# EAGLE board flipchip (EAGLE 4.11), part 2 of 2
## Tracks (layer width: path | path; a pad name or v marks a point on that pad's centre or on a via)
A1  (via drill 0.61)
  Top 0.254: D29.2 148.59,58.89 147.31,58.89 D30.1 | v130.17,65.24 v130.17,62.06
  Bottom 0.254: 130.17,60.16 144.78,60.16 146.05,58.89 D30.1 | 130.17,60.16 129.53,60.16 128.27,58.89 IN3-4.13 | IC5.11 26.66,62.06 28.57,60.16 49.52,60.16 50.8,61.43 SV1.10 51.43,60.8 52.7,60.8 52.7,58.25 55.24,55.72 81.27,55.72 86.35,60.8 92.07,60.8 95.88,64.61 126.36,64.61 127.63,65.88 129.53,65.88 v130.17,65.24 | v130.17,62.06 130.17,60.16
A1I
  Top 0.254: IC10.11 106.67,63.33 107.94,64.61 126.99,64.61 126.99,63.97 127.63,63.33 127.63,62.06 IN3-4.15
B1  (via drill 0.61)
  Top 0.254: D39.2 148.59,69.05 147.31,69.05 D40.1 | v32.38,69.69 25.39,69.69 24.12,68.42 IC6.3 | v45.08,67.14 46.35,65.88 46.35,62.06 SV1.6 46.35,60.8 46.35,60.16 59.69,60.16 60.32,60.8 60.32,85.56 v65.4,85.56 | v120.64,84.29 120.64,83.02 122.55,81.12 122.55,69.05 124.45,69.05 IN5-6.2
  Bottom 0.254: IN5-6.2 125.72,69.05 126.99,67.78 144.78,67.78 146.05,69.05 D40.1 | v32.38,69.69 42.54,69.69 v45.08,67.14 | v120.64,84.29 109.85,84.29 108.58,83.02 97.78,83.02 95.24,85.56 v65.4,85.56
B1I
  Bottom 0.254: IC11.3 104.13,68.42 106.04,70.32 122.55,70.32 123.82,71.59 124.45,71.59 IN5-6.4
C1  (via drill 0.61)
  Top 0.254: v34.92,58.89 34.92,72.86 33.65,74.13 IC6.8 | SV1.3 44.45,58.89 45.72,58.89 SV1.5 46.98,58.89 48.26,58.89 SV1.7 49.52,58.89 50.8,58.89 SV1.9 52.06,58.89 53.34,58.89 SV1.11 54.61,58.89 55.88,58.89 SV1.13 57.15,58.89 58.41,58.89 SV1.15 | SV1.19 63.49,58.89 62.23,58.89 SV1.17 | SV1.23 69.84,58.89 71.11,58.89 SV1.25 72.38,58.89 73.65,58.89 SV1.27 74.92,58.89 76.19,58.89 SV1.29 | 80.64,58.89 80,58.89 SV1.31 | 80.64,58.89 81.27,58.89 SV1.33 | v83.18,74.77 80.64,72.23 80.64,58.89
  Bottom 0.254: D33.2 148.59,71.59 147.31,71.59 D34.1 146.05,71.59 144.78,70.32 126.36,70.32 126.36,72.23 125.09,73.5 IN5-6.6 124.45,74.13 123.82,73.5 97.15,73.5 96.52,72.86 95.24,72.86 93.34,74.77 v83.18,74.77 | v34.92,58.89 40.63,58.89 SV1.1 41.91,58.89 43.18,58.89 SV1.3 | SV1.17 60.95,58.89 59.69,58.89 SV1.15 | SV1.19 64.77,58.89 66.03,58.89 SV1.21 67.3,58.89 68.58,58.89 SV1.23 | SV1.31 78.73,58.89 77.46,58.89 SV1.29
C1I  (via drill 0.61)
  Top 0.254: v123.82,70.32 123.82,74.77 125.09,76.03 IN5-6.8
  Bottom 0.254: v123.82,70.32 123.18,69.69 113.02,69.69 111.75,68.42 IC11.6
D1  (via drill 0.61)
  Top 0.254: v47.62,65.88 48.89,64.61 | 48.89,64.61 48.89,62.06 SV1.8 | 130.17,70.95 v132.07,72.86 | 130.17,70.95 128.27,69.05 IN5-6.1 | 48.89,64.61 52.7,64.61 52.7,85.56 53.97,86.83 70.48,86.83 70.48,81.75 72.38,79.84 78.1,79.84 v78.1,43.02 | v131.44,37.3 135.25,41.11 135.25,50.64 134.62,51.27 134.62,66.51 130.17,70.95
  Bottom 0.254: v47.62,65.88 33.02,65.88 31.75,67.14 IC6.6 | v132.07,72.86 144.78,72.86 146.05,74.13 D36.1 147.31,74.13 148.59,74.13 D35.2 | v78.1,43.02 78.73,42.38 89.53,42.38 92.7,39.2 129.53,39.2 v131.44,37.3
D1I
  Bottom 0.254: IC11.8 114.29,75.4 125.72,75.4 126.36,74.77 126.36,73.5 127.63,72.23 IN5-6.3
D2  (via drill 0.61)
  Top 0.254: v125.09,15.07 125.09,17.62 IN1-2.2 | v38.09,41.75 38.09,22.7 29.21,22.7 24.12,17.62 IC20.3 | v75.56,41.75 76.83,43.02 76.83,45.56 SV2.6 | v89.53,13.8 88.26,15.07 v88.26,37.94
  Bottom 0.254: D1.1 148.59,13.17 147.31,13.17 D2.2 146.05,13.17 144.78,14.44 140.33,14.44 139.7,15.07 v125.09,15.07 124.45,14.44 100.96,14.44 99.69,15.71 99.05,15.07 90.8,15.07 v89.53,13.8 | v38.09,41.75 39.37,43.02 50.16,43.02 50.8,42.38 68.58,42.38 69.21,41.75 v75.56,41.75 84.45,41.75 v88.26,37.94
D2I
  Bottom 0.254: IC2.3 103.5,18.25 105.4,20.16 118.1,20.16 119.38,21.43 125.09,21.43 IN1-2.4
E1  (via drill 0.61)
  Top 0.254: v158.75,5.55 157.47,6.82 157.47,72.86 151.12,72.86 150.49,73.5 150.49,74.77 149.22,76.03 D37.2
  Bottom 0.254: IN5-6.5 128.27,74.13 139.06,74.13 140.33,75.4 144.78,75.4 146.05,76.67 D38.1 147.31,76.67 148.59,76.67 D37.2 | 29.84,64.61 29.84,69.05 29.21,69.69 26.03,69.69 26.03,74.13 IC6.11 | 29.84,64.61 48.89,64.61 50.8,62.7 52.06,62.7 53.34,61.43 SV1.12 | v158.75,5.55 156.84,3.64 142.87,3.64 141.6,2.38 85.72,2.38 84.45,3.64 79.37,3.64 77.46,1.74 23.49,1.74 8.25,16.98 7.62,16.98 6.98,17.62 6.98,64.61 29.84,64.61
E1I
  Bottom 0.254: IC11.11 106.67,76.03 108.58,77.94 125.72,77.94 126.99,76.67 IN5-6.7
E2  (via drill 0.61)
  Top 0.254: v145.41,19.52 145.41,17.62 146.68,16.34 D4.2 | v62.86,24.6 v65.4,24.6 | v74.29,24.6 75.56,25.87 75.56,40.47 74.29,41.75 74.29,45.56 SV2.8 | v122.55,20.16 125.09,22.7 IN1-2.6
  Bottom 0.254: v145.41,19.52 139.06,19.52 136.52,22.06 126.99,22.06 125.72,23.33 IN1-2.6 | D3.1 148.59,15.71 147.31,15.71 D4.2 | v62.86,24.6 34.28,24.6 IC20.8 | v65.4,24.6 v74.29,24.6 74.92,25.23 78.1,25.23 78.73,24.6 90.8,24.6 93.34,22.06 102.23,22.06 102.23,15.71 102.86,15.07 104.77,15.07 104.77,18.25 106.04,19.52 118.74,19.52 119.38,20.16 v122.55,20.16
E2I  (via drill 0.61)
  Top 0.254: v121.28,18.88 121.28,21.43 125.09,25.23 IN1-2.8
  Bottom 0.254: v121.28,18.88 113.02,18.88 111.75,17.62 IC2.6
F1  (via drill 0.61)
  Top 0.254: v113.02,72.23 v120.01,79.21
  Bottom 0.254: D47.2 148.59,79.21 147.31,79.21 D48.1 146.05,79.21 144.78,77.94 126.99,77.94 125.72,79.21 IN5-6.10 124.45,79.21 v120.01,79.21 | 62.86,64.61 52.7,64.61 39.37,77.94 26.03,77.94 24.12,79.84 IC7.3 | 62.86,64.61 65.4,62.06 65.4,60.16 58.41,60.16 57.15,61.43 SV1.14 | v113.02,72.23 71.11,72.23 70.48,71.59 70.48,64.61 62.86,64.61
F1I  (via drill 0.61)
  Top 0.254: v104.77,92.55 104.77,83.02 103.5,81.75 IC12.3 | v116.83,93.18 119.38,90.64 119.38,86.83 124.45,81.75 IN5-6.12
  Bottom 0.254: v104.77,92.55 106.04,93.81 116.2,93.81 v116.83,93.18
F2  (via drill 0.61)
  Top 0.254: SV2.10 71.75,46.83 71.75,47.46 66.03,47.46 65.4,46.83 65.4,39.2 60.32,34.12 60.32,15.07 v59.69,14.44 v67.94,6.18 | v156.21,2.38 156.21,16.98 151.12,16.98 149.86,18.25 D5.1 | v84.45,2.38 77.46,2.38 v77.46,3.01 | v74.29,3.01 73.65,3.01 73.02,2.38 71.75,2.38 v71.75,3.64
  Bottom 0.254: IN1-2.1 128.27,18.25 129.53,16.98 144.78,16.98 146.05,18.25 D6.2 147.31,18.25 148.59,18.25 D5.1 | v59.69,14.44 33.65,14.44 31.75,16.34 IC20.6 | v156.21,2.38 155.57,1.74 85.08,1.74 v84.45,2.38 | v74.29,3.01 v77.46,3.01 | v71.75,3.64 70.48,3.64 v67.94,6.18
F2I
  Bottom 0.254: IC2.8 114.29,23.96 122.55,23.96 124.45,22.06 125.72,22.06 126.99,20.79 IN1-2.3
H1  (via drill 0.61)
  Top 0.254: v53.97,85.56 57.78,85.56 57.78,63.33 59.05,62.06 SV1.16 | IN5-6.14 125.09,84.92 123.82,86.2 v123.82,90.01 123.82,93.81 125.72,95.72 125.72,99.53 133.98,99.53 134.62,98.9 134.62,93.18 v133.98,92.55
  Bottom 0.254: D42.1 147.31,81.75 148.59,81.75 D41.2 149.22,82.39 150.49,83.66 150.49,85.56 155.57,85.56 156.21,86.2 156.21,88.1 151.76,88.1 149.22,90.64 138.43,90.64 136.52,92.55 v133.98,92.55 | IC7.8 34.28,87.47 36.19,85.56 v53.97,85.56 55.24,86.83 88.26,86.83 91.43,90.01 v123.82,90.01
H1I  (via drill 0.61)
  Top 0.254: v140.97,96.36 140.97,101.44 123.82,101.44 112.39,90.01 112.39,83.02 111.12,81.75 IC12.6 | v138.43,95.72 136.52,93.81 v136.52,87.47
  Bottom 0.254: v140.97,96.36 140.33,95.72 v138.43,95.72 | v136.52,87.47 135.89,88.1 126.99,88.1 125.72,86.83 IN5-6.16
H2  (via drill 0.61)
  Top 0.254: D7.1 148.59,20.79 147.31,20.79 D8.2 | v36.82,41.75 36.82,27.77 29.21,27.77 26.66,25.23 IC20.11 | v69.21,43.02 69.21,45.56 SV2.12 | v139.06,20.79 139.06,4.28 114.93,4.28 114.93,18.25 v111.12,22.06 | v95.88,25.23 95.88,29.04 94.61,30.32 v94.61,44.92
  Bottom 0.254: 140.33,22.06 139.7,22.7 128.9,22.7 128.27,23.33 IN1-2.5 | 140.33,22.06 144.78,22.06 146.05,20.79 D8.2 | v36.82,41.75 38.73,43.65 50.8,43.65 51.43,43.02 v69.21,43.02 73.02,43.02 74.29,44.28 93.97,44.28 v94.61,44.92 | v139.06,20.79 140.33,22.06 | v111.12,22.06 110.48,22.7 97.78,22.7 97.15,23.33 97.15,25.23 v95.88,25.23
H2I
  Bottom 0.254: IC2.11 106.67,25.23 108.58,27.14 125.72,27.14 126.99,25.87 IN1-2.7
J1  (via drill 0.61)
  Top 0.254: v40,71.59 39.37,72.23 | 39.37,72.23 31.75,79.84 IC7.6 | v123.82,95.09 125.09,96.36 125.09,100.17 134.62,100.17 135.25,99.53 135.25,75.4 133.98,75.4 130.17,79.21 128.27,79.21 IN5-6.9 | v115.56,95.72 112.39,98.9 112.39,102.7 111.12,103.98 39.37,103.98 39.37,72.23
  Bottom 0.254: IN5-6.9 128.27,79.21 130.17,79.21 133.98,83.02 144.78,83.02 146.05,84.29 D44.1 147.31,84.29 148.59,84.29 D43.2 | v40,71.59 40.63,70.95 45.08,70.95 52.06,63.97 60.95,63.97 63.49,61.43 SV1.20 | v123.82,95.09 123.18,94.45 116.83,94.45 v115.56,95.72
J1I  (via drill 0.61)
  Top 0.254: v116.2,82.39 116.2,84.29 113.66,86.83 IC12.8 | v123.18,81.75 124.45,80.48 126.99,80.48 126.99,81.75 IN5-6.11
  Bottom 0.254: v116.2,82.39 116.83,81.75 v123.18,81.75
J2  (via drill 0.61)
  Top 0.254: D16.1 148.59,23.33 147.31,23.33 D15.2 | SV2.14 66.67,45.56 66.67,38.57 v65.4,37.3 65.4,33.49 67.94,30.95 67.94,7.46 v69.21,6.18 | v120.01,9.99 120.01,22.7 125.09,27.77 IN1-2.10
  Bottom 0.254: IN1-2.10 125.72,28.41 126.99,27.14 128.27,27.14 129.53,25.87 139.06,25.87 140.33,24.6 144.78,24.6 146.05,23.33 D15.2 | v65.4,37.3 40,37.3 38.09,39.2 32.38,39.2 32.38,28.41 31.75,27.77 25.39,27.77 24.12,29.04 IC1.3 | v120.01,9.99 119.38,10.63 103.5,10.63 102.86,9.99 100.32,9.99 96.52,6.18 v69.21,6.18
J2I
  Bottom 0.254: IC3.3 104.13,29.04 105.4,27.77 119.38,27.77 122.55,30.95 124.45,30.95 IN1-2.12
K1  (via drill 0.61)
  Top 0.254: v32.38,73.5 32.38,76.67 29.84,79.21 29.84,83.02 26.03,86.83 IC7.11 | v62.86,80.48 62.86,63.33 61.59,62.06 SV1.18
  Bottom 0.254: D45.2 148.59,86.83 147.31,86.83 D46.1 146.05,86.83 144.78,85.56 140.33,85.56 139.06,84.29 128.27,84.29 IN5-6.13 126.99,84.29 125.72,83.02 116.83,83.02 116.2,83.66 110.48,83.66 109.21,82.39 97.15,82.39 96.52,83.02 83.81,83.02 80.64,79.84 71.11,79.84 70.48,80.48 v62.86,80.48 | v32.38,73.5 35.55,70.32 44.45,70.32 51.43,63.33 59.05,63.33 60.95,61.43 SV1.18
K1I  (via drill 0.61)
  Top 0.254: v106.04,92.55 106.04,89.37 IC12.11 | v126.36,92.55 126.36,88.73 127.63,87.47 IN5-6.15
  Bottom 0.254: v106.04,92.55 106.67,91.91 125.72,91.91 v126.36,92.55
K2  (via drill 0.61)
  Top 0.254: 125.09,32.86 126.36,31.59 126.36,30.32 126.99,29.68 v133.34,29.68 | 125.09,32.86 IN1-2.14 125.09,32.86 | v59.05,34.76 64.13,39.84 64.13,45.56 SV2.16 64.13,46.83 65.4,48.09 65.4,50 72.38,50 73.02,49.36 73.02,45.56 70.48,43.02 v70.48,4.92 | 125.09,32.86 122.55,30.32 122.55,27.14 116.83,21.43 v116.83,9.36 | v103.5,6.18 v103.5,9.36
  Bottom 0.254: v133.34,29.68 147.31,29.68 147.95,29.04 147.95,26.5 | 147.95,26.5 146.68,26.5 D9.2 | 147.95,26.5 148.59,25.87 D10.1 | v59.05,34.76 36.19,34.76 34.28,36.66 IC1.8 | v116.83,9.36 116.2,9.99 104.13,9.99 v103.5,9.36 | v103.5,6.18 102.23,4.92 v70.48,4.92
K2I  (via drill 0.61)
  Top 0.254: v115.56,35.39 111.12,30.95 IC3.6
  Bottom 0.254: v115.56,35.39 116.2,36.03 124.45,36.03 IN1-2.16
L1  (via drill 0.61)
  Top 0.254: IC8.3 64.13,69.05 69.21,63.97 69.21,62.06 SV1.24 | 81.91,9.99 75.56,3.64 75.56,3.01 74.29,1.74 48.89,1.74 48.89,12.54 D55.2 | 81.91,9.99 86.99,15.07 IN7-8.2 | v79.37,56.98 80.64,55.72 80.64,32.86 82.54,30.95 82.54,16.34 81.91,15.71 81.91,9.99
  Bottom 0.254: D56.1 46.98,13.17 48.26,13.17 D55.2 | v79.37,56.98 70.48,56.98 70.48,59.53 69.21,60.8 SV1.24
L1I
  Bottom 0.254: IC13.3 69.84,13.8 71.11,12.54 72.38,12.54 73.02,13.17 73.02,18.88 86.99,18.88 IN7-8.4
L2  (via drill 0.61)
  Top 0.254: D12.1 148.59,28.41 147.31,28.41 D11.2 | v35.55,51.27 35.55,35.39 31.11,30.95 IC1.6 | v58.41,51.27 60.32,49.36 60.32,48.09 61.59,46.83 SV2.18 61.59,45.56 57.78,41.75 57.78,32.22 57.15,31.59 57.15,15.71 v66.03,6.82 | v121.91,11.27 121.91,11.9 123.18,13.17 123.18,19.52 125.72,19.52 126.36,20.16 126.36,26.5 127.63,27.77 IN1-2.9
  Bottom 0.254: IN1-2.9 128.27,28.41 129.53,27.14 144.78,27.14 146.05,28.41 D11.2 | v35.55,51.27 v58.41,51.27 | v121.91,11.27 121.28,11.9 81.91,11.9 77.46,7.46 66.67,7.46 v66.03,6.82
L2I
  Top 0.254: IC3.8 114.29,36.66 123.82,36.66 123.82,35.39 124.45,34.76 125.72,34.76 126.36,34.12 126.36,32.86 127.63,31.59 IN1-2.11
M1  (via drill 0.61)
  Top 0.254: IC8.8 74.29,76.67 75.56,75.4 75.56,63.33 74.29,62.06 SV1.28 | v84.45,15.71 84.45,17.62 86.99,20.16 IN7-8.6 | v54.61,7.46 50.16,11.9 50.16,13.8 48.89,15.07 D49.2 | v93.34,73.5 93.97,72.86 93.97,65.24 92.07,63.33 v92.07,22.06
  Bottom 0.254: v84.45,15.71 76.83,8.09 55.24,8.09 v54.61,7.46 | D50.1 46.98,15.71 48.26,15.71 D49.2 | v93.34,73.5 78.73,73.5 74.92,77.31 IC8.8 | v92.07,22.06 88.89,22.06 87.62,20.79 IN7-8.6
M1I  (via drill 0.61)
  Top 0.254: v78.1,23.96 78.1,16.98 76.83,15.71 IC13.6
  Bottom 0.254: v78.1,23.96 86.99,23.96 IN7-8.8
M2  (via drill 0.61)
  Top 0.254: D14.1 148.59,30.95 147.31,30.95 D13.2 | v52.06,39.84 58.41,46.19 SV2.20
  Bottom 0.254: D13.2 146.05,30.95 144.78,32.22 129.53,32.22 128.27,33.49 IN1-2.13 126.99,33.49 125.72,32.22 121.91,32.22 121.28,32.86 92.07,32.86 85.08,39.84 v52.06,39.84 28.57,39.84 26.66,37.94 IC1.11
M2I
  Top 0.254: IC3.11 106.04,38.57 107.94,40.47 127.63,40.47 127.63,36.66 IN1-2.15
N1  (via drill 0.61)
  Top 0.254: v86.35,63.33 86.35,42.38 90.8,37.94 90.8,17.62 89.53,16.34 IN7-8.1 | D51.2 48.89,18.88 50.16,20.16 50.16,40.47 55.24,45.56 55.24,49.36 63.49,57.62 65.4,57.62 65.4,59.53 66.67,60.8 SV1.22
  Bottom 0.254: D52.1 46.98,18.25 48.26,18.25 D51.2 | 71.75,63.97 71.75,62.7 68.58,62.7 67.3,61.43 SV1.22 | 71.75,63.97 71.75,69.05 IC8.6 | v86.35,63.33 85.72,63.97 71.75,63.97
N1I  (via drill 0.61)
  Top 0.254: v80,17.62 80,20.16 79.37,20.79 IC13.8
  Bottom 0.254: v80,17.62 80.64,16.98 87.62,16.98 88.89,18.25 IN7-8.3
N2  (via drill 0.61)
  Top 0.254: v138.43,45.56 137.79,44.92 137.79,38.57 139.06,37.3 146.68,37.3 146.68,40.47 D24.1 147.31,41.11 148.59,41.11 D23.2 | v52.06,41.11 56.51,45.56 SV2.22 | v107.31,44.28 104.77,46.83 v104.77,51.91
  Bottom 0.254: v138.43,45.56 133.98,45.56 133.34,44.92 126.99,44.92 125.72,43.65 IN3-4.2 124.45,43.65 123.82,44.28 v107.31,44.28 | v52.06,41.11 51.43,40.47 25.39,40.47 24.12,41.75 IC4.3 | v104.77,51.91 60.32,51.91 57.78,49.36 57.78,46.83 56.51,46.83 SV2.22
N2I
  Bottom 0.254: IC9.3 104.13,43.02 106.67,45.56 125.09,45.56 IN3-4.4
N$1  (via drill 0.61)
  Top 0.254: v116.83,62.06 116.83,60.8 109.21,60.8 104.77,56.35 104.77,53.81 102.23,51.27 102.23,48.73 101.59,48.09 101.59,44.28 100.96,43.65 IC9.2 | v128.9,57.62 132.71,53.81 132.71,43.02 133.98,41.75 v133.98,41.11 | D24.2 143.5,41.11 142.87,41.11 RN4.11
  Bottom 0.254: v116.83,62.06 117.47,62.7 125.72,62.7 126.36,62.06 126.36,58.25 126.99,57.62 v128.9,57.62 | v133.98,41.11 140.33,41.11 RN4.11
N$2  (via drill 0.61)
  Top 0.254: RN3.11 153.03,41.11 152.4,41.11 D23.1 | v90.8,42.38 91.43,43.02 91.43,66.51 90.8,67.14 v90.8,95.09 | v138.43,94.45 139.06,93.81 139.06,76.67 135.89,73.5 135.89,56.98 139.06,53.81 139.06,47.46 136.52,44.92 v136.52,42.38
  Bottom 0.254: v90.8,42.38 97.78,42.38 IC9.1 | v90.8,95.09 112.39,95.09 114.93,97.62 125.72,97.62 126.99,98.9 133.98,98.9 v138.43,94.45 | v136.52,42.38 149.86,42.38 151.12,41.11 D23.1
N$3  (via drill 0.61)
  Top 0.254: RN1.11 153.03,13.17 152.4,13.17 D1.2 151.76,12.54 v151.76,9.99 | v100.96,8.72 100.96,15.71 IC2.2
  Bottom 0.254: v100.96,8.72 102.86,8.72 103.5,8.09 106.67,8.09 107.31,7.46 123.18,7.46 124.45,6.18 137.79,6.18 141.6,9.99 v151.76,9.99
N$4  (via drill 0.61)
  Top 0.254: v104.77,3.64 98.42,9.99 98.42,15.71 IC2.1 | v141.6,3.64 141.6,12.54 RN2.11 142.87,13.17 143.5,13.17 D2.1
  Bottom 0.254: v104.77,3.64 v141.6,3.64
N$5
  Top 0.254: D18.2 143.5,43.65 142.87,43.65 RN4.10
  Bottom 0.254: IC9.5 109.21,41.75 111.12,39.84 131.44,39.84 135.25,43.65 140.33,43.65 RN4.10
N$6
  Top 0.254: RN1.10 153.03,15.71 152.4,15.71 D3.2 151.76,15.07 150.49,13.8 150.49,1.74 111.75,1.74 108.58,4.92 108.58,15.71 IC2.5
N$7  (via drill 0.61)
  Top 0.254: v104.77,6.18 104.77,39.84 106.04,41.11 IC9.4 | v158.75,7.46 v158.75,44.28 | RN3.10 153.03,43.65 152.4,43.65 D17.1
  Bottom 0.254: v104.77,6.18 121.91,6.18 123.18,4.92 140.33,4.92 142.87,7.46 v158.75,7.46 | v158.75,44.28 155.57,47.46 151.12,47.46 150.49,46.83 150.49,44.28 151.76,44.28 D17.1
N$8  (via drill 0.61)
  Top 0.254: v120.64,43.02 120.64,45.56 115.56,45.56 111.75,49.36 IC9.9 | v131.44,43.02 132.71,41.75 v132.71,39.84 | D19.1 152.4,46.19 153.03,46.19 RN3.9
  Bottom 0.254: v120.64,43.02 121.28,42.38 128.9,42.38 129.53,43.02 v131.44,43.02 | v132.71,39.84 155.57,39.84 156.21,40.47 156.21,45.56 154.94,45.56 RN3.9
N$9  (via drill 0.61)
  Top 0.254: RN3.8 153.03,48.73 152.4,48.73 D21.1 151.76,48.09 150.49,46.83 150.49,36.66 v152.4,34.76 | v102.23,7.46 102.23,47.46 103.5,48.73 IC9.12
  Bottom 0.254: v102.23,7.46 106.04,7.46 106.67,6.82 122.55,6.82 123.82,5.55 138.43,5.55 140.97,8.09 153.03,8.09 158.75,13.8 158.75,34.76 v152.4,34.76
N$10  (via drill 0.61)
  Top 0.254: RN3.7 153.03,51.27 152.4,51.27 D31.1 | v97.15,65.88 97.15,57.62 98.42,56.35 IC10.1
  Bottom 0.254: v97.15,65.88 126.36,65.88 127.63,67.14 138.43,67.14 140.33,65.24 156.84,65.24 158.75,67.14 160.02,65.88 160.02,51.91 154.94,51.91 RN3.7
N$11  (via drill 0.61)
  Top 0.254: RN3.6 153.03,53.81 152.4,53.81 D25.1 | v100.96,57.62 99.69,58.89 v99.69,98.9 | v122.55,101.44 125.72,104.61 160.02,104.61 160.02,59.53 v158.75,58.25
  Bottom 0.254: v100.96,57.62 103.5,57.62 105.4,55.72 IC10.4 | v99.69,98.9 101.59,100.8 121.91,100.8 v122.55,101.44 | v158.75,58.25 154.94,54.44 RN3.6
N$12  (via drill 0.61)
  Top 0.254: v123.82,60.16 129.53,60.16 v129.53,58.89 | RN3.5 153.03,56.35 152.4,56.35 D27.1
  Bottom 0.254: v123.82,60.16 123.18,60.8 113.02,60.8 111.75,62.06 IC10.9 | v129.53,58.89 130.17,58.25 139.7,58.25 140.33,57.62 149.86,57.62 151.12,56.35 D27.1
N$13  (via drill 0.61)
  Top 0.254: RN3.4 153.03,58.89 152.4,58.89 D29.1 | v104.77,70.32 104.77,65.24 103.5,63.97 IC10.12 | v119.38,71.59 121.91,69.05 121.91,68.42 123.82,66.51 133.34,66.51 v133.34,62.06
  Bottom 0.254: v104.77,70.32 105.4,70.95 118.74,70.95 v119.38,71.59 | v133.34,62.06 133.98,62.7 147.31,62.7 151.12,58.89 D29.1
N$14  (via drill 0.61)
  Top 0.254: v133.34,56.98 133.34,57.62 128.9,62.06 128.9,63.33 127.63,64.61 127.63,65.24 106.04,65.24 104.77,63.97 104.77,60.8 106.67,60.8 107.94,62.06 IC10.10 | D28.2 143.5,56.35 142.87,56.35 RN4.5
  Bottom 0.254: v133.34,56.98 133.98,56.35 140.33,56.35 RN4.5
N$15  (via drill 0.61)
  Top 0.254: D20.2 143.5,46.19 142.87,46.19 RN4.9 140.97,45.56 139.7,44.28 139.7,39.2 v139.06,38.57 | v131.44,38.57 128.9,41.11 121.28,41.11 119.38,43.02 119.38,44.92 113.66,44.92 109.21,49.36 IC9.10
  Bottom 0.254: v131.44,38.57 v139.06,38.57
N$16  (via drill 0.61)
  Top 0.254: RN4.8 142.87,48.73 143.5,48.73 D22.2 144.14,48.09 145.41,46.83 v145.41,38.57 | v93.34,100.17 93.34,81.12 94.61,79.84 94.61,68.42 95.24,67.78 95.24,63.97 94.61,63.33 94.61,55.72 97.15,53.17 97.15,44.28 99.69,44.28 100.96,45.56 100.96,48.73 IC9.13
  Bottom 0.254: v93.34,100.17 97.78,104.61 154.3,104.61 161.28,97.62 161.28,37.3 147.95,37.3 146.68,38.57 v145.41,38.57
N$17  (via drill 0.61)
  Top 0.254: v99.69,45.56 99.69,52.54 100.96,53.81 IC10.2 | v114.93,47.46 v118.1,50.64 | v123.82,50 129.53,50 v129.53,50.64 | D32.2 143.5,51.27 142.87,51.27 RN4.7
  Bottom 0.254: v99.69,45.56 100.32,46.19 113.66,46.19 v114.93,47.46 | v118.1,50.64 118.74,50 v123.82,50 | v129.53,50.64 131.44,52.54 136.52,52.54 137.79,51.27 140.33,51.27 RN4.7
N$18
  Top 0.254: D26.2 143.5,53.81 142.87,53.81 RN4.6
  Bottom 0.254: IC10.5 109.21,54.44 110.48,53.17 123.82,53.17 124.45,52.54 129.53,52.54 130.17,53.17 137.16,53.17 137.79,53.81 140.33,53.81 RN4.6
N$19  (via drill 0.61)
  Top 0.254: RN4.4 142.87,58.89 143.5,58.89 D30.2 144.78,58.89 v148.59,62.7 | v100.96,58.89 100.96,61.43 IC10.13 | v90.16,58.25 90.16,94.45 v89.53,95.09 | v155.57,100.8 158.75,97.62 v158.75,65.88
  Bottom 0.254: v100.96,58.89 100.32,58.25 v90.16,58.25 | v89.53,95.09 95.88,101.44 121.28,101.44 122.55,102.7 142.24,102.7 144.14,100.8 v155.57,100.8 | v158.75,65.88 155.57,62.7 v148.59,62.7
N$20  (via drill 0.61)
  Top 0.254: v102.23,53.17 102.23,65.24 100.96,66.51 IC11.2 | v90.16,53.17 89.53,52.54 v89.53,40.47 | v109.21,34.12 109.85,33.49 v109.85,4.92 | v157.47,5.55 156.84,6.18 156.84,63.97 155.57,65.24 144.14,65.24 144.14,68.42 D40.2 143.5,69.05 142.87,69.05 RN6.11
  Bottom 0.254: v90.16,53.17 v102.23,53.17 | v89.53,40.47 95.88,34.12 v109.21,34.12 | v109.85,4.92 110.48,4.28 140.97,4.28 142.24,5.55 v157.47,5.55
N$21
  Top 0.254: D4.1 143.5,15.71 142.87,15.71 RN2.10
  Bottom 0.254: IC2.4 106.67,16.34 107.94,15.07 123.82,15.07 125.09,16.34 140.97,16.34 RN2.10
N$22  (via drill 0.61)
  Top 0.254: v92.7,70.95 92.07,71.59 v92.07,91.91 | v126.99,97.62 128.27,98.9 133.34,98.9 v133.34,97.62 | v146.68,93.18 147.95,91.91 147.95,70.95 148.59,70.32 151.76,70.32 151.76,69.69 D39.1 152.4,69.05 153.03,69.05 RN5.11
  Bottom 0.254: v92.7,70.95 96.52,70.95 98.42,69.05 IC11.1 | v92.07,91.91 94.61,94.45 113.02,94.45 115.56,96.99 126.36,96.99 v126.99,97.62 | v133.34,97.62 137.79,93.18 v146.68,93.18
N$23  (via drill 0.61)
  Top 0.254: RN1.9 153.03,18.25 152.4,18.25 D5.2 | v137.79,24.6 140.33,22.06 v147.95,22.06
  Bottom 0.254: v137.79,24.6 124.45,24.6 122.55,26.5 110.48,26.5 109.21,25.23 IC2.10 | v147.95,22.06 147.95,19.52 149.86,19.52 151.12,18.25 D5.2
N$24  (via drill 0.61)
  Top 0.254: v118.1,21.43 118.74,20.79 v118.74,17.62 | D6.1 143.5,18.25 142.87,18.25 RN2.9
  Bottom 0.254: v118.1,21.43 114.29,21.43 111.75,23.96 IC2.9 | v118.74,17.62 122.55,17.62 124.45,19.52 137.79,19.52 139.06,18.25 140.33,18.25 RN2.9
N$25  (via drill 0.61)
  Top 0.254: v120.64,67.14 120.64,65.88 110.48,65.88 109.21,67.14 IC11.5 | v123.82,67.78 126.36,67.78 126.36,72.23 126.99,72.86 v130.81,72.86 | D34.2 143.5,71.59 142.87,71.59 RN6.10
  Bottom 0.254: v120.64,67.14 121.28,67.78 v123.82,67.78 | v130.81,72.86 132.07,71.59 140.33,71.59 RN6.10
N$26
  Top 0.254: IC6.2 20.32,68.42 18.41,70.32 8.25,70.32 8.25,69.69 OUT5-6.2
N$33
  Top 0.254: IC4.5 27.94,43.02 26.03,44.92 10.79,44.92 10.79,44.28 OUT3-4.1
N$34
  Bottom 0.254: IC4.4 25.39,43.02 22.22,46.19 11.43,46.19 OUT3-4.3
N$35
  Bottom 0.254: IC4.12 22.86,49.36 20.95,47.46 12.7,47.46 11.43,48.73 OUT3-4.5
N$36
  Bottom 0.254: IC4.13 20.32,50.64 19.05,51.91 10.79,51.91 OUT3-4.7
N$49
  Bottom 0.254: IC4.1 18.41,43.65 17.14,44.92 10.16,44.92 8.88,46.19 OUT3-4.4
N$50
  Top 0.254: IC4.9 30.48,49.36 28.57,47.46 8.25,47.46 8.25,48.09 OUT3-4.6
N$51
  Bottom 0.254: IC4.2 20.32,41.75 19.05,40.47 12.06,40.47 8.88,43.65 OUT3-4.2
N$52
  Top 0.254: IC4.10 27.94,50.64 26.03,52.54 8.25,52.54 8.25,51.91 OUT3-4.8
N$53
  Top 0.254: IC20.5 27.94,16.34 26.66,15.07 10.79,15.07 10.79,17.62 OUT1-2.1
N$54
  Bottom 0.254: IC20.4 25.39,17.62 22.22,20.79 11.43,20.79 OUT1-2.3
N$55
  Bottom 0.254: IC20.12 22.86,23.96 20.95,22.06 12.7,22.06 11.43,23.33 OUT1-2.5
N$56
  Bottom 0.254: IC20.13 20.32,25.23 19.05,26.5 10.79,26.5 OUT1-2.7
N$57
  Bottom 0.254: IC20.2 20.32,16.34 19.05,15.07 12.06,15.07 8.88,18.25 OUT1-2.2
N$58
  Bottom 0.254: IC20.1 18.41,18.25 17.14,19.52 10.16,19.52 8.88,20.79 OUT1-2.4
N$59
  Bottom 0.254: IC20.9 30.48,23.96 27.94,21.43 12.06,21.43 11.43,22.06 10.16,22.06 8.88,23.33 OUT1-2.6
N$60
  Top 0.254: IC20.10 27.94,23.96 26.03,22.06 9.52,22.06 9.52,23.96 8.25,25.23 OUT1-2.8
N$61
  Bottom 0.254: IC1.13 20.32,37.94 19.05,39.2 14.6,39.2 11.43,36.03 OUT1-2.15
N$62
  Top 0.254: IC1.12 22.86,36.66 19.68,33.49 11.43,33.49 OUT1-2.13
N$63
  Bottom 0.254: IC1.4 25.39,30.32 23.49,32.22 12.7,32.22 11.43,30.95 OUT1-2.11
N$64
  Top 0.254: IC1.5 27.94,29.04 26.66,27.77 10.79,27.77 OUT1-2.9
N$65
  Bottom 0.254: IC1.2 20.32,29.04 18.41,27.14 10.16,27.14 8.88,28.41 OUT1-2.10
N$66
  Top 0.254: IC1.1 17.77,29.68 8.25,29.68 8.25,30.32 OUT1-2.12
N$67
  Top 0.254: IC1.9 30.48,36.66 26.03,32.22 8.25,32.22 8.25,32.86 OUT1-2.14
N$68
  Bottom 0.254: IC1.10 27.94,36.66 26.03,34.76 10.16,34.76 8.88,36.03 OUT1-2.16
N$69
  Bottom 0.254: IC5.2 20.32,54.44 18.41,52.54 10.16,52.54 8.88,53.81 OUT3-4.10
N$70
  Top 0.254: IC5.1 17.77,55.08 8.25,55.08 8.25,55.72 OUT3-4.12
N$71
  Top 0.254: IC5.9 30.48,62.06 26.03,57.62 8.25,57.62 8.25,58.25 OUT3-4.14
N$72
  Top 0.254: IC5.10 27.94,62.06 26.03,60.16 8.25,60.16 8.25,60.8 OUT3-4.16
N$73
  Bottom 0.254: IC5.13 20.32,62.06 18.41,60.16 12.7,60.16 11.43,61.43 OUT3-4.15
N$74
  Bottom 0.254: IC5.12 22.86,62.06 19.68,58.89 11.43,58.89 OUT3-4.13
N$75
  Bottom 0.254: IC5.4 25.39,55.72 23.49,57.62 12.7,57.62 11.43,56.35 OUT3-4.11
N$76
  Top 0.254: IC5.5 27.94,54.44 26.66,53.17 10.79,53.17 OUT3-4.9
N$81
  Bottom 0.254: IC6.5 27.94,67.14 26.66,65.88 14.6,65.88 11.43,69.05 OUT5-6.1
N$82
  Bottom 0.254: IC6.4 25.39,68.42 22.22,71.59 11.43,71.59 OUT5-6.3
N$83
  Bottom 0.254: IC6.12 22.86,74.77 20.95,72.86 12.7,72.86 11.43,74.13 OUT5-6.5
N$84
  Bottom 0.254: IC6.13 20.32,76.03 19.05,77.31 10.79,77.31 OUT5-6.7
N$85
  Bottom 0.254: IC8.5 68.58,69.69 66.67,67.78 50.8,67.78 47.62,70.95 47.62,72.86 49.52,72.86 50.8,71.59 OUT7-8.1
N$86
  Bottom 0.254: IC8.4 66.03,70.95 62.86,74.13 52.06,74.13 OUT7-8.3
N$87
  Bottom 0.254: IC8.12 64.13,76.67 64.13,75.4 53.34,75.4 52.06,76.67 OUT7-8.5
N$88
  Bottom 0.254: IC8.13 60.95,78.58 59.69,79.84 51.43,79.84 OUT7-8.7
N$89
  Bottom 0.254: IC6.1 18.41,69.05 17.14,70.32 10.16,70.32 8.88,71.59 OUT5-6.4
N$90
  Top 0.254: IC6.9 30.48,74.77 28.57,72.86 8.25,72.86 8.25,73.5 OUT5-6.6
N$91
  Bottom 0.254: IC6.10 27.94,76.03 26.66,77.31 20.32,77.31 19.68,77.94 10.16,77.94 8.88,76.67 OUT5-6.8
N$92
  Top 0.254: IC7.5 27.94,81.12 26.03,83.02 12.06,83.02 12.06,81.12 10.79,79.84 OUT5-6.9
N$93
  Bottom 0.254: IC7.4 25.39,81.12 23.49,83.02 12.7,83.02 11.43,81.75 OUT5-6.11
N$95
  Top 0.254: IC7.12 22.86,87.47 19.68,84.29 11.43,84.29 OUT5-6.13
N$96
  Bottom 0.254: IC7.13 20.32,88.73 19.05,90.01 14.6,90.01 11.43,86.83 OUT5-6.15
N$97
  Top 0.254: IC7.2 20.32,79.84 18.41,77.94 8.25,77.94 8.25,78.58 OUT5-6.10
N$98
  Bottom 0.254: IC7.1 17.77,80.48 10.16,80.48 8.88,81.75 OUT5-6.12
N$99
  Bottom 0.254: IC7.9 30.48,87.47 26.66,83.66 12.06,83.66 11.43,83.02 10.16,83.02 8.88,84.29 OUT5-6.14
N$100
  Bottom 0.254: IC7.10 27.94,87.47 26.03,85.56 10.16,85.56 8.88,86.83 OUT5-6.16
N$113
  Top 0.254: IC21.13 60.95,90.01 59.05,88.1 51.43,88.1 51.43,88.73 OUT7-8.15
N$114
  Top 0.254: IC21.12 63.49,90.01 60.95,87.47 51.43,87.47 OUT7-8.13
N$115
  Bottom 0.254: IC21.4 66.03,83.66 64.13,85.56 55.24,85.56 53.97,84.29 52.06,84.29 OUT7-8.11
N$116
  Bottom 0.254: IC21.5 68.58,82.39 67.3,81.12 63.49,81.12 62.86,81.75 62.86,84.92 60.95,84.92 60.32,84.29 60.32,81.12 51.43,81.12 OUT7-8.9
N$117
  Bottom 0.254: IC21.2 61.59,81.75 61.59,80.48 50.8,80.48 49.52,81.75 OUT7-8.10
N$118
  Bottom 0.254: IC21.1 58.41,83.02 50.8,83.02 49.52,84.29 OUT7-8.12
N$119
  Top 0.254: IC21.9 71.11,91.28 69.84,92.55 50.16,92.55 50.16,88.73 48.89,87.47 OUT7-8.14
N$120
  Bottom 0.254: IC21.10 68.58,91.28 67.3,92.55 52.7,92.55 49.52,89.37 OUT7-8.16
N$121
  Bottom 0.254: IC8.10 68.58,77.31 66.03,74.77 52.7,74.77 52.06,75.4 48.26,75.4 47.62,76.03 47.62,79.21 48.26,79.21 OUT7-8.8
N$122
  Bottom 0.254: IC8.9 71.11,78.58 69.84,79.84 63.49,79.84 62.86,79.21 62.86,76.03 58.41,76.03 57.78,76.67 57.78,77.94 50.8,77.94 49.52,76.67 OUT7-8.6
N$123
  Bottom 0.254: IC8.1 59.05,71.59 57.78,72.86 50.8,72.86 49.52,74.13 OUT7-8.4
N$137
  Bottom 0.254: IC8.2 60.95,69.69 59.69,68.42 52.7,68.42 49.52,71.59 OUT7-8.2
N$138  (via drill 0.61)
  Top 0.254: RN1.8 153.03,20.79 152.4,20.79 D7.2 | v100.96,20.79 100.96,23.33 IC2.13 | v98.42,19.52 97.15,18.25 v97.15,9.36 | v124.45,7.46 126.99,4.92 138.43,4.92 138.43,8.72 v137.79,9.36
  Bottom 0.254: v100.96,20.79 99.69,19.52 v98.42,19.52 | v97.15,9.36 97.78,9.99 99.05,9.99 99.69,10.63 102.23,10.63 102.86,11.27 120.64,11.27 v124.45,7.46 | v137.79,9.36 140.33,11.9 149.86,11.9 150.49,12.54 150.49,16.98 155.57,16.98 156.21,17.62 156.21,20.16 154.94,20.16 RN1.8
N$139  (via drill 0.61)
  Top 0.254: v103.5,21.43 103.5,23.33 IC2.12 | v113.02,21.43 115.56,18.88 115.56,9.36 116.83,8.09 123.82,8.09 124.45,8.72 126.36,8.72 126.36,8.09 128.27,6.18 135.89,6.18 135.89,18.88 139.06,22.06 140.33,20.79 RN2.8 142.87,20.79 143.5,20.79 D8.1
  Bottom 0.254: v103.5,21.43 104.13,20.79 112.39,20.79 v113.02,21.43
N$140  (via drill 0.61)
  Top 0.254: v107.31,77.94 107.31,70.32 106.04,69.05 IC11.4 | v130.17,80.48 v133.98,76.67 | v139.06,75.4 145.41,75.4 145.41,68.42 146.05,67.78 156.21,67.78 156.21,69.69 154.94,70.95 RN5.10 153.03,71.59 152.4,71.59 D33.1
  Bottom 0.254: v107.31,77.94 107.94,78.58 118.1,78.58 120.01,80.48 v130.17,80.48 | v133.98,76.67 135.25,75.4 v139.06,75.4
N$141  (via drill 0.61)
  Top 0.254: RN1.7 153.03,23.33 152.4,23.33 D16.2 | v94.61,13.8 v94.61,26.5 | v125.72,7.46 127.63,5.55 137.16,5.55 v137.16,7.46
  Bottom 0.254: v94.61,26.5 97.78,26.5 100.32,29.04 IC3.2 | v94.61,13.8 95.24,13.17 123.18,13.17 125.72,10.63 v125.72,7.46 | v137.16,7.46 140.97,11.27 154.94,11.27 156.84,13.17 156.84,22.7 154.94,22.7 RN1.7
N$142  (via drill 0.61)
  Top 0.254: v99.69,14.44 99.69,27.14 98.42,28.41 IC3.1 | v126.36,13.8 136.52,23.96 136.52,24.6 137.79,25.87 139.7,25.87 139.7,25.23 140.97,23.96 RN2.7 142.87,23.33 143.5,23.33 D15.1
  Bottom 0.254: v99.69,14.44 100.32,13.8 v126.36,13.8
N$143  (via drill 0.61)
  Top 0.254: v118.1,87.47 118.1,82.39 111.75,76.03 IC11.9 | v150.49,88.1 150.49,76.03 151.76,74.77 D35.1 152.4,74.13 153.03,74.13 RN5.9
  Bottom 0.254: v118.1,87.47 119.38,88.73 139.7,88.73 140.33,88.1 v150.49,88.1
N$144  (via drill 0.61)
  Top 0.254: RN1.6 153.03,25.87 152.4,25.87 D10.2 | v121.28,31.59 v123.18,33.49
  Bottom 0.254: v121.28,31.59 110.48,31.59 109.21,30.32 IC3.5 | v123.18,33.49 124.45,34.76 133.98,34.76 134.62,34.12 139.7,34.12 140.33,34.76 147.31,34.76 150.49,31.59 150.49,26.5 151.76,26.5 D10.2
N$145
  Top 0.254: IC3.4 106.04,30.95 107.31,32.22 107.31,38.57 107.94,39.2 126.36,39.2 126.36,35.39 126.99,34.76 133.34,34.76 133.34,36.66 134.62,37.94 137.16,37.94 137.16,35.39 140.33,32.22 145.41,32.22 145.41,27.77 144.14,26.5 D9.1 143.5,25.87 142.87,25.87 RN2.6
N$146  (via drill 0.61)
  Top 0.254: v98.42,77.94 97.15,79.21 v97.15,96.36 | v157.47,90.64 156.84,90.01 156.84,79.21 154.94,77.31 RN5.8 153.03,76.67 152.4,76.67 D37.1
  Bottom 0.254: v98.42,77.94 100.96,77.94 102.86,76.03 IC11.12 | v97.15,96.36 98.42,97.62 112.39,97.62 113.66,98.9 124.45,98.9 125.72,100.17 139.7,100.17 141.6,98.26 145.41,98.26 153.03,90.64 v157.47,90.64
N$147  (via drill 0.61)
  Top 0.254: v107.31,8.72 107.31,30.95 107.94,31.59 107.94,35.39 108.58,36.03 IC3.10 | v111.12,8.72 114.29,5.55 114.29,3.64 115.56,2.38 147.95,2.38 147.95,18.88 148.59,19.52 150.49,19.52 150.49,26.5 151.76,27.77 D12.2 152.4,28.41 153.03,28.41 RN1.5
  Bottom 0.254: v107.31,8.72 v111.12,8.72
N$148  (via drill 0.61)
  Top 0.254: RN2.5 142.87,28.41 143.5,28.41 D11.1 | v115.56,34.12 v121.28,28.41
  Bottom 0.254: v115.56,34.12 111.12,34.12 111.12,36.03 IC3.9 | v121.28,28.41 122.55,29.68 132.07,29.68 133.34,28.41 140.33,28.41 RN2.5
N$149  (via drill 0.61)
  Top 0.254: RN5.7 153.03,79.21 152.4,79.21 D47.1 | v95.88,79.84 94.61,81.12 v94.61,91.91 | v127.63,90.64 133.98,84.29 v133.98,80.48
  Bottom 0.254: v95.88,79.84 97.78,79.84 IC12.1 | v94.61,91.91 95.24,91.28 126.99,91.28 v127.63,90.64 | v133.98,80.48 149.86,80.48 151.12,79.21 D47.1
N$150  (via drill 0.61)
  Top 0.254: RN1.4 153.03,30.95 152.4,30.95 D14.2 | v97.15,19.52 97.15,32.22 100.96,36.03 IC3.13 | v123.18,11.9 134.62,23.33 v134.62,35.39
  Bottom 0.254: v97.15,19.52 97.15,16.98 88.89,16.98 88.26,16.34 88.26,12.54 122.55,12.54 v123.18,11.9 | v134.62,35.39 136.52,37.3 146.68,37.3 153.03,30.95 RN1.4
N$151  (via drill 0.61)
  Top 0.254: v109.85,35.39 v112.39,35.39 | v134.62,36.66 140.33,30.95 RN2.4 142.87,30.95 143.5,30.95 D13.1
  Bottom 0.254: v109.85,35.39 105.4,35.39 104.13,36.66 IC3.12 | v112.39,35.39 114.29,35.39 116.2,37.3 130.17,37.3 131.44,36.03 133.98,36.03 v134.62,36.66
N$152  (via drill 0.61)
  Top 0.254: v107.31,98.9 107.31,83.02 106.04,81.75 IC12.4 | D41.1 152.4,81.75 153.03,81.75 RN5.6
  Bottom 0.254: v107.31,98.9 108.58,100.17 122.55,100.17 123.82,101.44 140.97,101.44 142.87,99.53 154.3,99.53 158.75,95.09 158.75,82.39 154.94,82.39 RN5.6
N$153  (via drill 0.61)
  Top 0.254: D43.1 152.4,84.29 153.03,84.29 RN5.5 154.94,84.92 156.21,86.2 156.21,97.62 v151.76,102.07 | v111.12,102.7 111.12,89.37 IC12.9
  Bottom 0.254: v111.12,102.7 111.75,103.34 142.87,103.34 144.14,102.07 v151.76,102.07
N$154  (via drill 0.61)
  Top 0.254: RN5.4 153.03,86.83 152.4,86.83 D45.1 151.76,87.47 v151.76,90.64 | v103.5,96.36 103.5,89.37 IC12.12
  Bottom 0.254: v103.5,96.36 104.13,96.99 113.02,96.99 114.29,98.26 125.09,98.26 126.36,99.53 138.43,99.53 140.33,97.62 144.78,97.62 v151.76,90.64
N$155  (via drill 0.61)
  Top 0.254: v109.85,98.9 109.85,90.64 108.58,89.37 IC12.10 | v154.3,98.26 145.41,98.26 145.41,86.2 144.14,84.92 D44.2 143.5,84.29 142.87,84.29 RN6.5
  Bottom 0.254: v109.85,98.9 110.48,99.53 123.18,99.53 124.45,100.8 140.33,100.8 142.24,98.9 153.67,98.9 v154.3,98.26
N$156  (via drill 0.61)
  Top 0.254: v128.9,64.61 128.9,65.88 123.18,65.88 121.28,67.78 121.28,68.42 115.56,68.42 109.21,74.77 IC11.10 | v137.16,65.88 139.7,68.42 139.7,72.23 140.97,73.5 RN6.9 142.87,74.13 143.5,74.13 D36.2
  Bottom 0.254: v128.9,64.61 129.53,63.97 135.25,63.97 v137.16,65.88
N$157  (via drill 0.61)
  Top 0.254: v102.23,84.29 102.23,77.94 100.96,76.67 IC11.13 | v136.52,85.56 v136.52,76.67 | D38.2 143.5,76.67 142.87,76.67 RN6.8
  Bottom 0.254: v102.23,84.29 103.5,85.56 119.38,85.56 120.01,86.2 123.82,86.2 124.45,85.56 v136.52,85.56 | v136.52,76.67 140.33,76.67 RN6.8
N$158  (via drill 0.61)
  Top 0.254: D48.2 143.5,79.21 142.87,79.21 RN6.7 140.97,79.84 139.7,81.12 139.7,100.8 124.45,100.8 122.55,98.9 122.55,89.37 v120.64,87.47 | v100.96,84.29 100.96,81.75 IC12.2
  Bottom 0.254: v100.96,84.29 102.86,86.2 118.74,86.2 120.01,87.47 v120.64,87.47
N$159  (via drill 0.61)
  Top 0.254: v108.58,84.29 108.58,81.75 IC12.5 | v123.18,84.29 124.45,83.02 130.17,83.02 130.17,81.75 v132.07,79.84 | D42.2 143.5,81.75 142.87,81.75 RN6.6
  Bottom 0.254: v108.58,84.29 109.21,84.92 120.01,84.92 120.64,85.56 121.91,85.56 v123.18,84.29 | v132.07,79.84 133.98,81.75 140.33,81.75 RN6.6
N$160  (via drill 0.61)
  Top 0.254: v102.23,102.7 102.23,90.64 100.96,89.37 IC12.13 | v144.14,103.34 144.14,87.47 D46.2 143.5,86.83 142.87,86.83 RN6.4
  Bottom 0.254: v102.23,102.7 103.5,103.98 143.5,103.98 v144.14,103.34
N$161
  Top 0.254: RN8.11 42.54,13.17 43.18,13.17 D56.2
  Bottom 0.254: IC13.2 66.03,13.8 64.13,11.9 45.72,11.9 44.45,13.17 D56.2
N$162
  Top 0.254: RN7.11 52.7,13.17 52.06,13.17 D55.1
  Bottom 0.254: IC13.1 63.49,13.8 62.86,13.17 55.24,13.17 RN7.11
N$163  (via drill 0.61)
  Top 0.254: v45.08,11.27 45.08,13.8 43.81,15.07 D50.2 43.18,15.71 42.54,15.71 RN8.10
  Bottom 0.254: v45.08,11.27 72.38,11.27 74.29,13.17 IC13.5
N$164
  Top 0.254: RN7.10 52.7,15.71 52.06,15.71 D49.1
  Bottom 0.254: IC13.4 71.11,15.07 69.21,16.98 56.51,16.98 55.24,15.71 RN7.10
N$165
  Top 0.254: D51.1 52.06,18.25 52.7,18.25 RN7.9 54.61,17.62 55.88,16.34 55.88,3.64 70.48,3.64 75.56,8.72 75.56,19.52 76.83,20.79 IC13.9
N$166
  Top 0.254: RN7.8 52.7,20.79 52.06,20.79 D53.1
  Bottom 0.254: IC13.12 68.58,21.43 67.3,20.16 63.49,20.16 62.86,20.79 62.86,22.06 56.51,22.06 55.24,20.79 RN7.8
N$167
  Top 0.254: RN7.7 52.7,23.33 52.06,23.33 D63.1
  Bottom 0.254: IC14.1 64.13,25.87 64.13,23.96 63.49,23.96 62.86,23.33 55.24,23.33 RN7.7
N$168  (via drill 0.61)
  Top 0.254: D57.1 52.06,25.87 52.7,25.87 RN7.6 54.61,26.5 55.88,27.77 55.88,31.59 v56.51,32.22 | v71.75,30.95 71.75,28.41 IC14.4
  Bottom 0.254: v71.75,30.95 71.11,31.59 57.15,31.59 v56.51,32.22
N$169  (via drill 0.61)
  Top 0.254: RN7.5 52.7,28.41 52.06,28.41 D59.1 | v59.05,32.86 58.41,32.22 v58.41,28.41
  Bottom 0.254: v59.05,32.86 59.69,32.22 74.29,32.22 76.19,34.12 IC14.9 | v58.41,28.41 55.24,28.41 RN7.5
N$170  (via drill 0.61)
  Top 0.254: RN7.4 52.7,30.95 52.06,30.95 D61.1 | v69.21,29.68 69.21,33.49 IC14.12
  Bottom 0.254: v69.21,29.68 68.58,30.32 54.61,30.32 RN7.4
N$171  (via drill 0.61)
  Top 0.254: RN8.5 42.54,28.41 43.18,28.41 D60.2 43.81,29.04 45.08,30.32 45.08,44.28 v51.43,44.28 | v73.02,44.28 73.02,37.3 74.29,36.03 IC14.10
  Bottom 0.254: v51.43,44.28 v73.02,44.28
N$172  (via drill 0.61)
  Top 0.254: RN8.9 42.54,18.25 43.18,18.25 D52.2 | v73.02,10.63 73.02,19.52 74.29,20.79 IC13.10
  Bottom 0.254: v73.02,10.63 71.75,9.36 41.91,9.36 37.46,13.8 31.75,13.8 29.84,15.71 29.84,18.88 40.63,18.88 RN8.9
N$173  (via drill 0.61)
  Top 0.254: RN8.8 42.54,20.79 43.18,20.79 D54.2 | v62.86,18.25 66.03,21.43 IC13.13
  Bottom 0.254: v62.86,18.25 62.23,17.62 55.88,17.62 55.24,16.98 45.72,16.98 45.08,17.62 45.08,20.16 43.81,20.16 D54.2
N$174
  Top 0.254: RN8.7 42.54,23.33 43.18,23.33 D64.2
  Bottom 0.254: IC14.2 66.67,28.41 66.67,29.68 36.19,29.68 32.38,25.87 32.38,22.7 40.63,22.7 RN8.7
N$175
  Top 0.254: RN8.6 42.54,25.87 43.18,25.87 D58.2
  Bottom 0.254: IC14.5 73.65,26.5 72.38,25.23 66.03,25.23 65.4,25.87 65.4,29.04 63.49,29.04 62.86,28.41 62.86,27.14 45.72,27.14 44.45,25.87 D58.2
N$176  (via drill 0.61)
  Top 0.254: RN8.4 42.54,30.95 43.18,30.95 D62.2 | v56.51,36.03 55.24,34.76 51.43,34.76 v51.43,33.49
  Bottom 0.254: v56.51,36.03 57.15,36.66 64.77,36.66 66.03,35.39 IC14.13 | v51.43,33.49 50.8,32.86 46.35,32.86 44.45,30.95 D62.2
P1  (via drill 0.61)
  Top 0.254: IC8.11 67.3,77.31 73.02,71.59 73.02,60.8 73.65,60.16 76.19,60.16 76.19,61.43 SV1.30 | v93.97,63.97 93.34,63.33 v93.34,20.79
  Bottom 0.254: D54.1 46.98,20.79 48.26,20.79 D53.2 49.52,20.79 50.8,19.52 87.62,19.52 88.89,20.79 IN7-8.5 90.16,20.79 v93.34,20.79 | v93.97,63.97 88.26,63.97 84.45,60.16 78.73,60.16 77.46,61.43 SV1.30
P1I
  Bottom 0.254: IC13.11 72.38,21.43 73.65,20.16 84.45,20.16 86.35,22.06 87.62,22.06 88.89,23.33 IN7-8.7
P2  (via drill 0.61)
  Top 0.254: v130.81,50.64 130.81,47.46 126.99,47.46 125.72,48.73 IN3-4.6 | v147.95,50 147.95,45.56 146.68,44.28 D18.1 147.31,43.65 148.59,43.65 D17.2 | v116.83,95.72 116.83,104.61 38.73,104.61 38.73,90.64 10.16,90.64 6.98,87.47 6.98,65.88 30.48,65.88 32.38,63.97 32.38,52.54 33.65,51.27 IC4.8 | v125.72,94.45 125.09,93.81 v125.09,90.01 | v137.79,90.01 137.79,76.67 135.25,74.13 135.25,51.91 v135.89,51.27
  Bottom 0.254: IC4.8 34.28,50 54.61,50 55.24,49.36 55.24,46.83 53.97,46.83 SV2.24 | v130.81,50.64 131.44,50 135.89,50 | 135.89,50 v147.95,50 | v116.83,95.72 117.47,96.36 123.82,96.36 v125.72,94.45 | v125.09,90.01 125.72,89.37 137.16,89.37 v137.79,90.01 | v135.89,51.27 135.89,50
P2I  (via drill 0.61)
  Top 0.254: v133.98,44.28 v133.98,48.73
  Bottom 0.254: v133.98,44.28 130.17,40.47 113.02,40.47 111.75,41.75 IC9.6 | v133.98,48.73 133.34,49.36 128.9,49.36 128.27,50 126.99,50 125.72,51.27 IN3-4.8
R1  (via drill 0.61)
  Top 0.254: IC21.3 64.13,81.75 65.4,80.48 65.4,69.05 71.75,62.7 71.75,62.06 SV1.26 | 83.18,25.87 86.35,25.87 IN7-8.10 | 83.18,25.87 v83.18,62.7 | v39.37,10.63 39.37,22.06 44.45,22.06 45.72,23.33 D64.1 | v83.18,15.71 83.18,25.87
  Bottom 0.254: D64.1 46.98,23.33 48.26,23.33 D63.2 | v83.18,62.7 73.65,62.7 72.38,61.43 SV1.26 | v39.37,10.63 41.27,8.72 76.19,8.72 v83.18,15.71
R1I
  Bottom 0.254: IC14.3 69.84,27.77 71.11,29.04 86.99,29.04 IN7-8.12
R2  (via drill 0.61)
  Top 0.254: 128.27,44.92 v129.53,46.19 | 128.27,44.92 127.63,44.28 IN3-4.1 | v75.56,47.46 75.56,49.36 67.94,56.98 67.94,62.7 66.03,62.7 65.4,62.06 65.4,60.8 64.77,60.16 60.95,60.16 60.32,59.53 60.32,58.25 52.7,50.64 52.7,48.09 51.43,46.83 SV2.26 | v118.1,51.91 123.82,46.19 123.82,45.56 124.45,44.92 128.27,44.92
  Bottom 0.254: IC4.6 31.75,43.02 33.65,44.92 49.52,44.92 50.8,46.19 SV2.26 | v129.53,46.19 130.17,46.83 138.43,46.83 140.33,44.92 144.78,44.92 146.05,46.19 D20.1 147.31,46.19 148.59,46.19 D19.2 | v75.56,47.46 111.12,47.46 112.39,48.73 112.39,51.91 v118.1,51.91
R2I  (via drill 0.61)
  Top 0.254: v123.18,48.73 124.45,47.46 125.72,47.46 126.99,46.19 IN3-4.3
  Bottom 0.254: v123.18,48.73 122.55,49.36 114.29,49.36 IC9.8
S1  (via drill 0.61)
  Top 0.254: D57.2 48.26,25.87 46.98,25.87 D58.1 46.35,25.23 47.62,23.96 v47.62,7.46 | 79.37,83.66 79.37,62.06 SV1.32 | 79.37,83.66 79.37,84.29 74.29,89.37 IC21.8 | 79.37,83.66 85.08,77.94 85.08,33.49 86.99,31.59 IN7-8.14 | v73.02,3.64 81.27,11.9 v81.27,30.95
  Bottom 0.254: v47.62,7.46 52.7,2.38 71.75,2.38 v73.02,3.64 | v81.27,30.95 86.35,30.95 IN7-8.14
S1I  (via drill 0.61)
  Top 0.254: v80,30.95 80,30.32 77.46,27.77 IC14.6
  Bottom 0.254: v80,30.95 82.54,33.49 86.35,33.49 IN7-8.16
S2
  Bottom 0.254: D21.2 148.59,48.73 147.31,48.73 D22.1 146.05,48.73 144.78,47.46 129.53,47.46 128.27,48.73 IN3-4.5 126.99,48.73 125.72,47.46 116.2,47.46 114.93,48.73 113.02,46.83 84.45,46.83 82.54,44.92 73.65,44.92 73.02,45.56 72.38,44.92 53.34,44.92 52.7,45.56 52.7,47.46 46.98,47.46 | 46.98,47.46 40.63,47.46 40,48.09 27.94,48.09 26.66,49.36 IC4.11 | 46.98,47.46 48.26,46.19 SV2.28
S2I  (via drill 0.61)
  Top 0.254: v118.1,43.02 118.1,44.28 111.75,44.28 106.67,49.36 IC9.11 | v129.53,41.75 130.17,42.38 130.17,45.56 132.07,47.46 132.07,50.64 130.17,52.54 127.63,52.54 127.63,51.91 IN3-4.7
  Bottom 0.254: v118.1,43.02 119.38,41.75 v129.53,41.75
T2  (via drill 0.61)
  Top 0.254: v43.81,52.54 45.08,51.27 45.08,48.09 46.35,46.83 SV2.30 | 118.74,57.62 118.74,53.81 124.45,53.81 IN3-4.10 | 118.74,57.62 124.45,63.33 v126.36,63.33 | v137.16,63.97 139.7,61.43 139.7,53.17 140.33,52.54 146.68,52.54 146.68,51.91 D32.1 147.31,51.27 148.59,51.27 D31.2 | v116.83,59.53 118.74,57.62
  Bottom 0.254: 29.84,52.54 v43.81,52.54 | 29.84,52.54 26.03,52.54 24.12,54.44 IC5.3 | v126.36,63.33 136.52,63.33 v137.16,63.97 | 29.84,52.54 29.84,56.98 52.7,56.98 54.61,55.08 84.45,55.08 89.53,60.16 99.69,60.16 100.32,60.8 111.75,60.8 113.02,59.53 v116.83,59.53
T2I  (via drill 0.61)
  Top 0.254: v107.31,53.17 116.83,53.17 116.83,54.44 117.47,55.08 v117.47,56.35
  Bottom 0.254: v107.31,53.17 105.4,53.17 104.13,54.44 IC10.3 | v117.47,56.35 124.45,56.35 IN3-4.12
U1  (via drill 0.61)
  Top 0.254: D59.2 48.26,28.41 46.98,28.41 D60.1 46.35,29.04 47.62,30.32 v47.62,41.75 | IC21.6 71.75,84.29 73.02,85.56 73.02,91.91 71.11,93.81 45.72,93.81 45.72,69.05 43.81,67.14 43.81,62.06 SV1.4 43.81,60.8 42.54,59.53 42.54,58.25 40,55.72 40,45.56 v43.81,41.75 | v85.72,27.14 84.45,28.41 84.45,77.31 v80.64,81.12
  Bottom 0.254: v85.72,27.14 87.62,27.14 88.89,25.87 IN7-8.9 | v80.64,81.12 73.65,81.12 72.38,82.39 IC21.6 | v47.62,41.75 v43.81,41.75
U1I
  Bottom 0.254: IC14.8 80,34.76 87.62,34.76 88.26,34.12 88.26,32.22 90.16,32.22 90.8,31.59 90.8,29.04 89.53,29.04 IN7-8.11
U2  (via drill 0.61)
  Top 0.254: v38.09,46.83 38.09,53.17 33.65,57.62 33.65,61.43 IC5.8 | v136.52,55.08 137.79,53.81 v137.79,52.54 | D25.2 148.59,53.81 147.31,53.81 D26.1 | v50.16,52.54 50.16,44.92 43.18,44.92 41.91,46.19 SV2.34 | v114.29,58.25 v116.2,56.35
  Bottom 0.254: v38.09,46.83 38.73,46.19 40.63,46.19 SV2.34 | 126.36,55.08 126.36,56.98 125.09,58.25 IN3-4.14 | 126.36,55.08 v136.52,55.08 | v137.79,52.54 144.78,52.54 146.05,53.81 D26.1 | v50.16,52.54 83.18,52.54 90.16,59.53 100.32,59.53 100.96,60.16 111.12,60.16 113.02,58.25 v114.29,58.25 | v116.2,56.35 117.47,55.08 126.36,55.08
U2I  (via drill 0.61)
  Top 0.254: v120.01,57.62 123.82,61.43 124.45,61.43 IN3-4.16
  Bottom 0.254: v120.01,57.62 116.2,57.62 115.56,56.98 113.02,56.98 111.75,55.72 IC10.6
V1  (via drill 0.61)
  Top 0.254: v44.45,88.1 41.27,84.92 41.27,62.06 SV1.2 41.27,60.8 39.37,58.89 39.37,27.14 44.45,27.14 45.08,27.77 45.08,29.04 46.35,30.32 D62.1
  Bottom 0.254: IN7-8.13 88.89,30.95 87.62,29.68 70.48,29.68 69.21,30.95 56.51,30.95 55.24,32.22 50.8,32.22 49.52,30.95 D61.2 48.26,30.95 46.98,30.95 D62.1 | v44.45,88.1 64.13,88.1 66.03,90.01 IC21.11
V1I
  Bottom 0.254: IC14.11 72.38,35.39 73.65,36.66 86.99,36.66 89.53,34.12 IN7-8.15
V2  (via drill 0.61)
  Top 0.254: v41.27,53.81 42.54,52.54 42.54,48.09 43.81,46.83 SV2.32 | D27.2 148.59,56.35 147.31,56.35 D28.1 | v73.65,53.81 v76.83,50.64 | v109.85,51.91 116.83,51.91 118.1,53.17 123.82,53.17 124.45,52.54 126.99,52.54 126.99,53.81 IN3-4.9
  Bottom 0.254: IC5.6 31.75,54.44 33.02,53.17 40.63,53.17 v41.27,53.81 v73.65,53.81 | IN3-4.9 128.27,53.81 136.52,53.81 137.79,55.08 144.78,55.08 146.05,56.35 D28.1 | v76.83,50.64 77.46,50 96.52,50 97.15,49.36 97.15,48.09 109.21,48.09 109.85,48.73 v109.85,51.91
V2I  (via drill 0.61)
  Top 0.254: v118.1,59.53 118.1,63.97 116.83,63.97 116.2,63.33 114.29,63.33 IC10.8 | v123.18,58.89 124.45,57.62 127.63,57.62 127.63,56.98 IN3-4.11
  Bottom 0.254: v118.1,59.53 118.74,58.89 v123.18,58.89

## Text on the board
Top: VRS | Component Side
Bottom: Solder Side
tValues: FlipChip Interface- Rev. 1 | + | - | - | +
